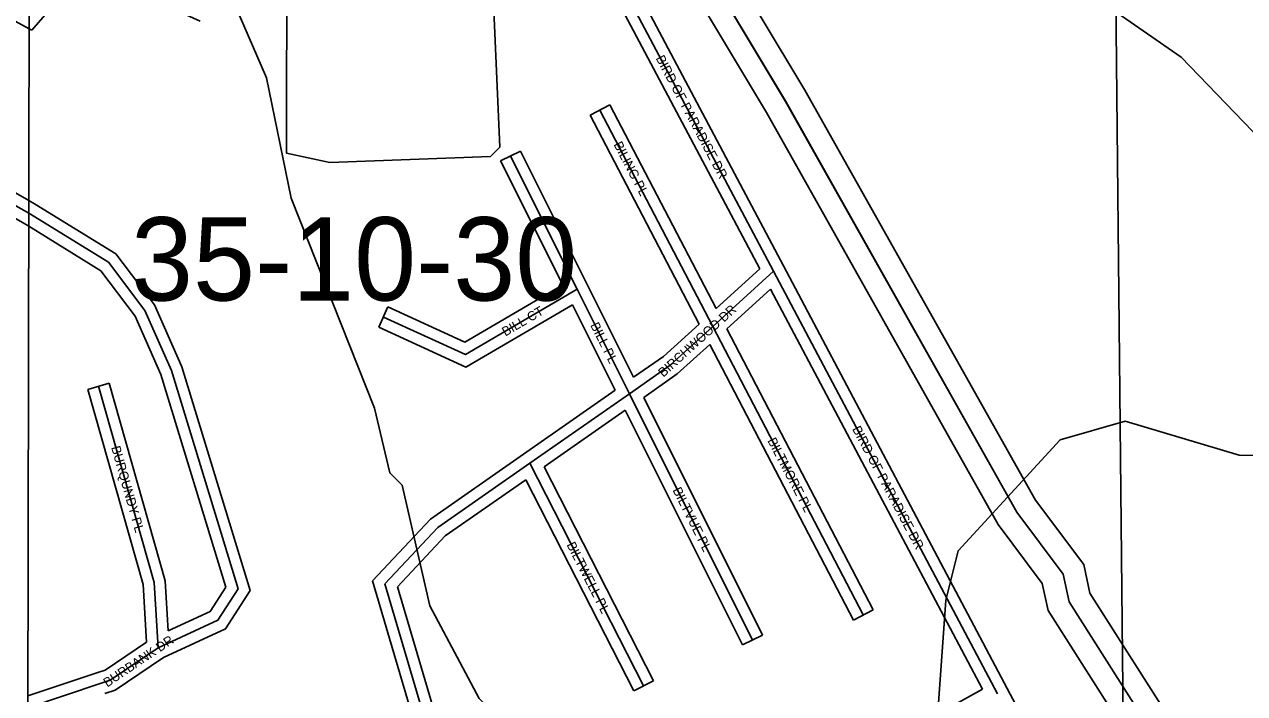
# Model space of a CAD drawing. Extents: x 457167 to 656239, y 1787309 to 1969297.
# Drawn here: x 576766 to 580059, y 1909774 to 1911582 of the extents above; entities that cross this region are included whole.
import ezdxf

# ---------------------------------------------------------------- set-up
doc = ezdxf.new("R2010")
doc.units = 0
for name, color, linetype in [('Level 1', 7, 'Continuous'), ('Level 13', 7, 'Continuous'), ('Level 14', 7, 'Continuous'), ('Level 2', 7, 'Continuous'), ('Level 31', 7, 'Continuous'), ('Level 32', 7, 'Continuous'), ('Level 34', 7, 'Continuous'), ('Level 5', 7, 'Continuous'), ('Level 63', 7, 'Continuous'), ('Level 7', 7, 'Continuous'), ('Level 8', 7, 'Continuous')]:
    doc.layers.add(name, color=color, linetype=linetype)

msp = doc.modelspace()

# ---------------------------------------------------------------- linework, layer by layer
at = {"layer": 'Level 1'}
msp.add_line((579691.072, 1913661.836), (579742.085, 1908632.671), dxfattribs=at)
at = {"layer": 'Level 13'}
msp.add_lwpolyline([(580924.16, 1907685.826), (580167.749, 1908987.76), (580043.06, 1909254.566), (579826.985, 1909596.836), (579818.524, 1909655.037), (579585.659, 1910022.435), (579569.285, 1910097.379), (579444.398, 1910264.186), (578820.866, 1911373.871), (578330.566, 1912191.644)], dxfattribs=at)
at = {"layer": 'Level 14'}
for points in [[(580976.04, 1907715.967), (580220.974, 1909015.588), (580095.816, 1909283.397), (579884.528, 1909618.086), (579876.058, 1909676.342), (579642.014, 1910045.601), (579625.124, 1910122.912), (579494.782, 1910297.004), (578872.76, 1911404.001), (578385.413, 1912216.85)], [(580872.28, 1907655.684), (580114.525, 1908959.931), (579990.304, 1909225.736), (579769.444, 1909575.588), (579760.99, 1909633.732), (579529.304, 1909999.269), (579513.448, 1910071.846), (579394.013, 1910231.37), (578768.972, 1911343.741), (578275.722, 1912166.436)]]:
    msp.add_lwpolyline(points, dxfattribs=at)
at = {"layer": 'Level 31'}
for p, q in [((578319.584, 1911350.561), (578624.441, 1910765.908)), ((578078.399, 1911226.34), (578258.494, 1910866.316)), ((578624.441, 1910765.908), (578788.125, 1910915.386)), ((578788.125, 1910915.386), (579392.209, 1909774.105)), ((578258.494, 1910866.316), (578399.343, 1910584.196)), ((578624.441, 1910765.908), (579030.298, 1909986.862)), ((578130.685, 1910396.396), (578399.343, 1910584.196)), ((578399.343, 1910584.196), (578731.376, 1909919.123)), ((578130.685, 1910396.396), (578437.42, 1909795.375)), ((576775.594, 1909736.376), (576974.038, 1909802.846))]:
    msp.add_line(p, q, dxfattribs=at)
for points in [[(577672.328, 1912188.674), (578332.237, 1911776.36), (578788.125, 1910915.386)], [(576152.072, 1911426.098), (576778.415, 1911071.653), (576778.453, 1911071.63)], [(576778.452, 1911071.63), (576992.993, 1910939.191), (577091.247, 1910809.16), (577163.052, 1910646.821), (577342.972, 1910057.698)], [(578258.494, 1910866.316), (577956.487, 1910689.86), (577735.164, 1910791.422)], [(578399.343, 1910584.196), (578509.48, 1910661.421), (578624.441, 1910765.908)], [(577127.128, 1909897.792), (577117.014, 1910074.181), (576966.532, 1910604.332)], [(577739.361, 1910071.036), (577882.08, 1910223.101), (578130.685, 1910396.396)], [(577127.128, 1909897.792), (577288.756, 1909972.721), (577342.972, 1910057.698)], [(577739.361, 1910071.036), (578058.745, 1908987.795), (578093.23, 1908910.993), (578145.204, 1908837.064), (578219.154, 1908783.452)], [(576974.038, 1909802.846), (576997.576, 1909810.796), (577127.128, 1909897.792)]]:
    msp.add_lwpolyline(points, dxfattribs=at)
at = {"layer": 'Level 32'}
for p, q in [((576649.511, 1911639.646), (576779.519, 1911570.011)), ((576779.518, 1911570.011), (576786.554, 1911566.242)), ((576152.205, 1911460.493), (576778.526, 1911106.061)), ((578346.185, 1911364.431), (578292.982, 1911336.689)), ((578346.185, 1911364.431), (578633.011, 1910814.36)), ((578292.982, 1911336.689), (578587.144, 1910772.549)), ((578105.229, 1911239.761), (578051.569, 1911212.917)), ((578105.229, 1911239.761), (578285.325, 1910879.738)), ((578051.569, 1911212.917), (578219.087, 1910878.037)), ((578633.01, 1910814.36), (578750.744, 1910921.875)), ((578814.64, 1910929.421), (579418.724, 1909788.139)), ((578285.336, 1910879.717), (578410.632, 1910628.751)), ((578661.706, 1910759.31), (578779.74, 1910867.1)), ((578779.741, 1910867.099), (579351.958, 1909786.023)), ((577722.652, 1910764.156), (577747.676, 1910818.689)), ((578245.965, 1910824.249), (578360.939, 1910593.954)), ((578661.706, 1910759.31), (579056.905, 1910000.722)), ((578615.818, 1910717.528), (579003.692, 1909973.001)), ((576937.672, 1910596.14), (576995.393, 1910612.524)), ((578113.497, 1910420.984), (578360.939, 1910593.954)), ((578437.73, 1910574.47), (578758.218, 1909932.523)), ((578169.28, 1910386.77), (578388.034, 1910539.686)), ((578388.034, 1910539.686), (578704.535, 1909905.722)), ((578169.28, 1910386.769), (578464.142, 1909809.011)), ((578119.609, 1910352.103), (578410.699, 1909781.736)), ((579056.905, 1910000.722), (579003.692, 1909973.001)), ((578758.218, 1909932.523), (578704.535, 1909905.722)), ((576775.662, 1909768.036), (576964.509, 1909831.293)), ((578464.142, 1909809.011), (578410.699, 1909781.736)), ((579351.957, 1909786.024), (579200.044, 1909701.409))]:
    msp.add_line(p, q, dxfattribs=at)
for points in [[(577713.488, 1912198.332), (578354.974, 1911797.528), (578814.638, 1910929.425)], [(577682.049, 1912147.226), (578309.499, 1911755.191), (578750.743, 1910921.875)], [(576786.554, 1911566.242), (576929.409, 1911731.539), (577241.147, 1911590.935)], [(576151.94, 1911391.701), (576763.143, 1911045.825), (576778.377, 1911036.421)], [(576778.525, 1911106.061), (576793.687, 1911097.481), (577013.538, 1910961.764), (577117.277, 1910824.473), (577191.217, 1910657.308), (577375.706, 1910053.226)], [(576778.376, 1911036.421), (576972.448, 1910916.616), (577065.217, 1910793.846), (577134.886, 1910636.334), (577310.239, 1910062.169)], [(578219.088, 1910878.037), (577954.821, 1910723.633), (577747.676, 1910818.689)], [(578245.965, 1910824.249), (577958.154, 1910656.086), (577722.652, 1910764.156)], [(578410.63, 1910628.751), (578490.704, 1910684.897), (578587.145, 1910772.549)], [(578437.73, 1910574.471), (578528.255, 1910637.945), (578615.818, 1910717.528)], [(577154.554, 1909943.573), (577146.776, 1910079.196), (576995.393, 1910612.524)], [(577096.198, 1909913.159), (577087.253, 1910069.166), (576937.672, 1910596.14)], [(577705.725, 1910079.036), (577862.351, 1910245.918), (578113.529, 1910421.007)], [(577772.998, 1910063.036), (577901.809, 1910200.282), (578119.609, 1910352.103)], [(577705.726, 1910079.036), (578030.544, 1908977.361), (578067.038, 1908896.086), (578123.542, 1908815.713), (578201.544, 1908759.163)], [(577141.891, 1909871.568), (577309.331, 1909949.191), (577375.706, 1910053.226)], [(577154.554, 1909943.573), (577268.182, 1909996.251), (577310.239, 1910062.169)], [(577772.997, 1910063.036), (578086.946, 1908998.228), (578119.423, 1908925.899), (578166.867, 1908858.415), (578214.154, 1908824.131)], [(576964.438, 1909831.271), (576984.179, 1909837.936), (577096.198, 1909913.158)], [(576983.638, 1909774.422), (577010.974, 1909783.655), (577141.892, 1909871.568)], [(579418.731, 1909788.126), (579628.76, 1909390.849), (579323.036, 1909016.155)]]:
    msp.add_lwpolyline(points, dxfattribs=at)
at = {"layer": 'Level 5'}
msp.add_lwpolyline([(577590.506, 1911208.566), (577473.834, 1911233.706), (577474.417, 1911792.239), (577982.993, 1911850.043), (578024.644, 1911825.003), (578049.042, 1911249.759), (578024.032, 1911224.778), (577590.506, 1911208.566)], close=True, dxfattribs=at)
at = {"layer": 'Level 63'}
for points in [[(536942.563, 1878385.707), (576708.29, 1878279.4), (576805.546, 1923734.416), (537088.612, 1923840.983), (536942.563, 1878385.707)], [(576708.289, 1878279.4), (616473.709, 1878215.526), (616521.962, 1923670.374), (576805.545, 1923734.416), (576708.289, 1878279.4)]]:
    msp.add_lwpolyline(points, dxfattribs=at)
at = {"layer": 'Level 7'}
for points in [[(580203.384, 1910417.857), (580044.991, 1910418.016), (579736.646, 1910510.046), (579561.554, 1910460.225), (579286.135, 1910160.406), (579252.656, 1910027.052), (579227.261, 1909660.294), (579185.383, 1909501.93), (578968.413, 1909268.743), (578734.96, 1909235.661), (578443.324, 1909369.332), (578176.789, 1909569.696), (577993.584, 1909761.63), (577860.469, 1910011.885), (577785.793, 1910337.072), (577752.482, 1910370.443), (577710.969, 1910545.577), (577486.499, 1911112.68), (577420.164, 1911437.857), (577312.059, 1911688.082), (577012.241, 1911971.848), (576887.259, 1912021.998), (576780.45, 1912005.661)], [(579671.19, 1911643.854), (579887.765, 1911493.571), (580129.232, 1911243.216)]]:
    msp.add_lwpolyline(points, dxfattribs=at)
at = {"layer": 'Level 8'}
msp.add_lwpolyline([(580167.522, 1908987.372), (580043.517, 1909254.378), (579826.509, 1909596.386), (579818.509, 1909655.386), (579585.501, 1910022.394), (579569.499, 1910097.396), (579444.496, 1910264.399), (578820.473, 1911373.423), (578330.455, 1912191.44), (578288.454, 1912316.443), (578064.445, 1912742.451), (578042.444, 1912791.453), (577299.413, 1914418.488), (577242.41, 1914544.491), (577450.412, 1914619.494), (579402.426, 1915482.525), (579711.428, 1915649.531), (581203.445, 1915779.541)], dxfattribs=at)

# ---------------------------------------------------------------- texts
at = {"layer": 'Level 2'}
msp.add_text('35-10-30', height=225, dxfattribs=at).set_placement((577054.092, 1910836.025))
at = {"layer": 'Level 34'}
for s, height, rotation, p in [('BIRD OF PARADISE DR', 25, 297.900933, (578469.547, 1911490.332)), ('BILING PL', 25, 297.538664, (578355.662, 1911257.608)), ('BILL CT', 25, 30.296139, (578064.438, 1910738.457)), ('BIRCHWOOD DR', 25, 42.266789, (578490.76, 1910627.516)), ('BILL PL', 25, 296.530339, (578292.834, 1910769.551)), ('BIRD OF PARADISE DR', 25, 297.892003, (578999.555, 1910489.219)), ('BURQUNDY PL', 24.99916, 285.845981, (577000.338, 1910439.463)), ('BILTMORE PL', 25, 297.517622, (578770.882, 1910457.761)), ('BILTVUE PL', 25, 296.529883, (578515.136, 1910324.275)), ('BILTWELL PL', 25, 297.037397, (578228.894, 1910176.468)), ('BURBANK DR', 25, 33.881492, (576990.093, 1909790.716))]:
    msp.add_text(s, height=height, rotation=rotation, dxfattribs=at).set_placement(p)

doc.saveas('drawing.dxf')
